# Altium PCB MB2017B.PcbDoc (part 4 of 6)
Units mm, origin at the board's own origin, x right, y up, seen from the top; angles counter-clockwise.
Board outline 148.19 x 169.19 mm, 4 copper layers (Top Layer, Mid Layer 1, Mid Layer 2, Bottom Layer), stack 1.498 mm thick; 458 components, 208 nets, 1223 pads, 6162 vias.
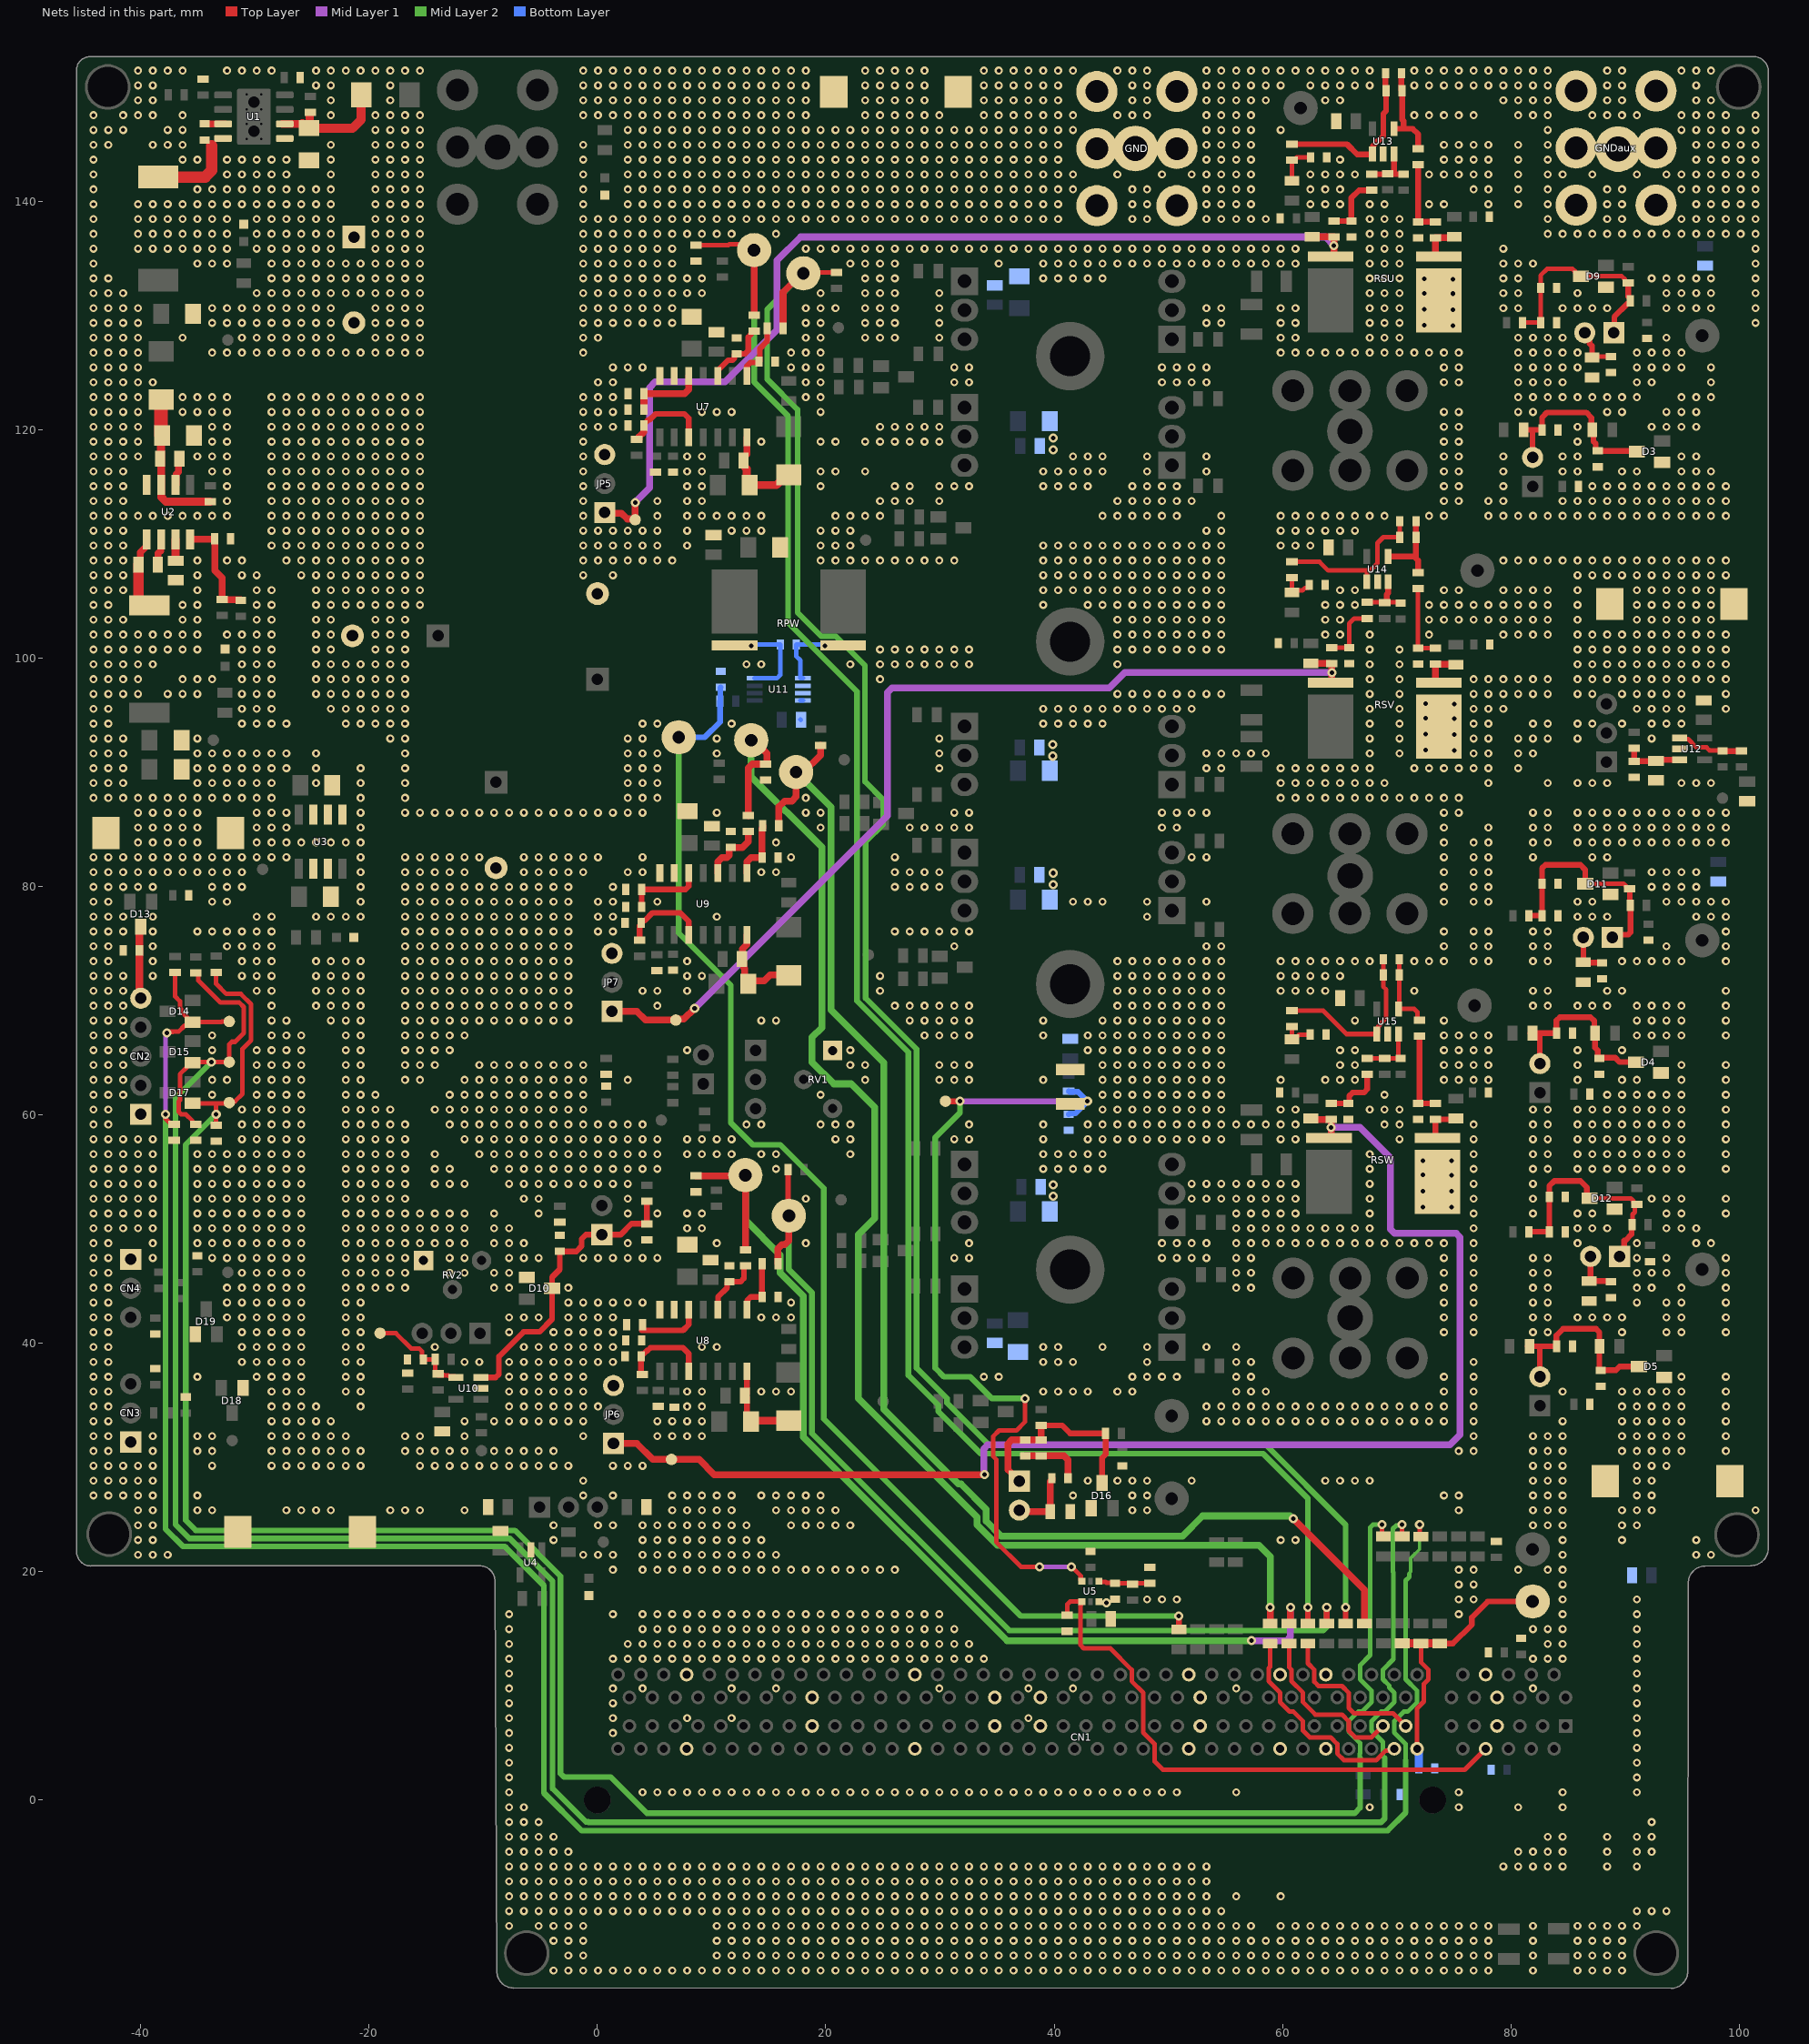
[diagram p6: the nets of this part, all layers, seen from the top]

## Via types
v1: diameter 0.7, hole 0.35, Top Layer to Bottom Layer, tented both sides, 5935 vias
v2: diameter 0.8, hole 0.4, Top Layer to Bottom Layer, tented both sides, 216 vias
v3: diameter 1, hole 0.5, Top Layer to Bottom Layer, tented both sides, 9 vias
v4: diameter 0.8, hole 0.4, Top Layer to Bottom Layer, 2 vias

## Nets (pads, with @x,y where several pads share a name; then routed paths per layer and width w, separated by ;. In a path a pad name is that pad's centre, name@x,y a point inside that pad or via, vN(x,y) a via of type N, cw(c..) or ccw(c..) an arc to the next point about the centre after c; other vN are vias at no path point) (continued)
GND: (continued)
  other v1: 48.147,112.484 49.447,112.484 50.747,112.484 54.647,112.484 59.847,112.484 61.147,112.484 62.447,112.484 63.747,112.484 65.047,112.484 66.347,112.484 67.647,112.484 68.947,112.484 72.847,112.484 74.147,112.484 78.047,112.484 79.347,112.484 80.647,112.484 81.947,112.484 83.247,112.484 84.547,112.484 85.847,112.484 87.147,112.484 88.447,112.484 89.747,112.484 91.047,112.484 92.347,112.484 93.647,112.484 94.947,112.484 96.247,112.484 97.547,112.484 98.847,112.484 -44.153,113.784 -42.853,113.784 -41.553,113.784 -32.453,113.784 -28.553,113.784 -27.253,113.784 -25.953,113.784 -24.653,113.784 -23.353,113.784 -22.053,113.784 -20.753,113.784 -19.453,113.784 -18.153,113.784 -16.853,113.784 -15.553,113.784 -1.253,113.784 5.247,113.784 7.847,113.784 9.147,113.784 24.747,113.784 26.047,113.784 27.347,113.784 29.947,113.784 45.547,113.784 46.847,113.784 48.147,113.784 49.447,113.784 50.747,113.784 52.047,113.784 74.147,113.784 75.447,113.784 78.047,113.784 79.347,113.784 84.547,113.784 85.847,113.784 87.147,113.784 88.447,113.784 89.747,113.784 91.047,113.784 92.347,113.784 93.647,113.784 94.947,113.784 96.247,113.784 97.547,113.784 98.847,113.784 -44.153,115.084 -42.853,115.084 -41.553,115.084 -32.453,115.084 -28.553,115.084 -27.253,115.084 -25.953,115.084 -24.653,115.084 -23.353,115.084 -22.053,115.084 -20.753,115.084 -19.453,115.084 -18.153,115.084 -16.853,115.084 -15.553,115.084 -1.253,115.084 7.847,115.084 9.147,115.084 19.547,115.084 26.047,115.084 27.347,115.084 29.947,115.084 31.247,115.084 32.547,115.084 39.047,115.084 40.347,115.084 41.647,115.084 42.947,115.084 46.847,115.084 48.147,115.084 49.447,115.084 50.747,115.084 74.147,115.084 75.447,115.084 79.347,115.084 87.147,115.084 88.447,115.084 89.747,115.084 91.047,115.084 92.347,115.084 93.647,115.084 94.947,115.084 96.247,115.084 97.547,115.084 98.847,115.084 -44.153,116.384 -42.853,116.384 -41.553,116.384 -33.753,116.384 -32.453,116.384 -28.553,116.384 -27.253,116.384 -25.953,116.384 -24.653,116.384 -23.353,116.384 -22.053,116.384 -20.753,116.384 -19.453,116.384 -18.153,116.384 -16.853,116.384 -15.553,116.384 -1.253,116.384 7.847,116.384 9.147,116.384 19.547,116.384 20.847,116.384 23.447,116.384 39.047,116.384 40.347,116.384 41.647,116.384 42.947,116.384 44.247,116.384 48.147,116.384 53.347,116.384 74.147,116.384 75.447,116.384 79.347,116.384 84.547,116.384 85.847,116.384 89.747,116.384 91.047,116.384 94.947,116.384 96.247,116.384 97.547,116.384 -44.153,117.684 -42.853,117.684 -41.553,117.684 -40.253,117.684 -35.053,117.684 -33.753,117.684 -32.453,117.684 -28.553,117.684 -27.253,117.684 -25.953,117.684 -24.653,117.684 -23.353,117.684 -22.053,117.684 -20.753,117.684 -19.453,117.684 -18.153,117.684 -16.853,117.684 -15.553,117.684 -1.253,117.684 7.847,117.684 9.147,117.684 41.647,117.684 42.947,117.684 44.247,117.684 48.147,117.684 53.347,117.684 74.147,117.684 75.447,117.684 79.347,117.684 84.547,117.684 85.847,117.684 94.947,117.684 96.247,117.684 -44.153,118.984 -42.853,118.984 -41.553,118.984 -40.253,118.984 -33.753,118.984 -32.453,118.984 -28.553,118.984 -27.253,118.984 -25.953,118.984 -24.653,118.984 -23.353,118.984 -22.053,118.984 -20.753,118.984 -19.453,118.984 -18.153,118.984 -16.853,118.984 -15.553,118.984 -1.253,118.984 14.347,118.984 19.547,118.984 20.847,118.984 23.447,118.984 24.747,118.984 26.047,118.984 27.347,118.984 28.647,118.984 29.947,118.984 74.147,118.984 75.447,118.984 85.847,118.984 -44.153,120.284 -42.853,120.284 -41.553,120.284 -40.253,120.284 -33.753,120.284 -32.453,120.284 -28.553,120.284 -27.253,120.284 -25.953,120.284 -24.653,120.284 -23.353,120.284 -22.053,120.284 -20.753,120.284 -19.453,120.284 -18.153,120.284 -16.853,120.284 -15.553,120.284 -1.253,120.284 0.047,120.284 1.347,120.284 24.747,120.284 26.047,120.284 27.347,120.284 28.647,120.284 29.947,120.284 74.147,120.284 75.447,120.284 85.847,120.284 92.347,120.284 93.647,120.284 94.947,120.284 96.247,120.284 -44.153,121.584 -42.853,121.584 -41.553,121.584 -40.253,121.584 -36.353,121.584 -35.053,121.584 -33.753,121.584 -32.453,121.584 -28.553,121.584 -27.253,121.584 -25.953,121.584 -24.653,121.584 -23.353,121.584 -22.053,121.584 -20.753,121.584 -19.453,121.584 -18.153,121.584 -16.853,121.584 -15.553,121.584 -1.253,121.584 0.047,121.584 1.347,121.584 9.147,121.584 10.447,121.584 11.747,121.584 19.547,121.584 74.147,121.584 75.447,121.584 80.647,121.584 81.947,121.584 88.447,121.584 89.747,121.584 93.647,121.584 94.947,121.584 96.247,121.584 -44.153,122.884 -42.853,122.884 -41.553,122.884 -40.253,122.884 -36.353,122.884 -35.053,122.884 -33.753,122.884 -32.453,122.884 -28.553,122.884 -27.253,122.884 -25.953,122.884 -24.653,122.884 -23.353,122.884 -22.053,122.884 -20.753,122.884 -19.453,122.884 -18.153,122.884 -16.853,122.884 -15.553,122.884 -1.253,122.884 0.047,122.884 1.347,122.884 18.247,122.884 19.547,122.884 80.647,122.884 81.947,122.884 83.247,122.884 84.547,122.884 85.847,122.884 87.147,122.884 88.447,122.884 89.747,122.884 91.047,122.884 94.947,122.884 96.247,122.884 97.547,122.884 -44.153,124.184 -42.853,124.184 -41.553,124.184 -40.253,124.184 -38.953,124.184 0.047,124.184 1.347,124.184 18.247,124.184 19.547,124.184 31.247,124.184 32.547,124.184 49.447,124.184 50.747,124.184 52.047,124.184 53.347,124.184 74.147,124.184 75.447,124.184 80.647,124.184 81.947,124.184 83.247,124.184 84.547,124.184 91.047,124.184 92.347,124.184 97.547,124.184 -44.153,125.484 -42.853,125.484 -41.553,125.484 -40.253,125.484 1.347,125.484 2.647,125.484 3.947,125.484 16.947,125.484 18.247,125.484 19.547,125.484 31.247,125.484 32.547,125.484 49.447,125.484 50.747,125.484 52.047,125.484 53.347,125.484 74.147,125.484 75.447,125.484 80.647,125.484 81.947,125.484 83.247,125.484 84.547,125.484 85.847,125.484 91.047,125.484 92.347,125.484 93.647,125.484 94.947,125.484 97.547,125.484 -44.153,126.784 -42.853,126.784 -41.553,126.784 -40.253,126.784 -33.753,126.784 -32.453,126.784 -31.153,126.784 -29.853,126.784 -28.553,126.784 -27.253,126.784 -25.953,126.784 -24.653,126.784 -23.353,126.784 -22.053,126.784 -20.753,126.784 -19.453,126.784 -18.153,126.784 -16.853,126.784 -15.553,126.784 -1.253,126.784 16.947,126.784 18.247,126.784 19.547,126.784 59.847,126.784 61.147,126.784 62.447,126.784 63.747,126.784 65.047,126.784 66.347,126.784 67.647,126.784 68.947,126.784 70.247,126.784 71.547,126.784 72.847,126.784 74.147,126.784 75.447,126.784 80.647,126.784 81.947,126.784 83.247,126.784 84.547,126.784 85.847,126.784 91.047,126.784 92.347,126.784 93.647,126.784 94.947,126.784 -44.153,128.084 -42.853,128.084 -41.553,128.084 -40.253,128.084 -36.353,128.084 -31.153,128.084 -29.853,128.084 -28.553,128.084 -27.253,128.084 -25.953,128.084 -24.653,128.084 -23.353,128.084 -19.453,128.084 -18.153,128.084 -16.853,128.084 -15.553,128.084 -1.253,128.084 0.047,128.084 18.247,128.084 19.547,128.084 23.447,128.084 24.747,128.084 26.047,128.084 29.947,128.084 59.847,128.084 61.147,128.084 67.647,128.084 68.947,128.084 70.247,128.084 80.647,128.084 81.947,128.084 83.247,128.084 84.547,128.084 93.647,128.084 -44.153,129.384 -42.853,129.384 -41.553,129.384 -40.253,129.384 -33.753,129.384 -32.453,129.384 -31.153,129.384 -29.853,129.384 -28.553,129.384 -27.253,129.384 -25.953,129.384 -24.653,129.384 -23.353,129.384 -19.453,129.384 -18.153,129.384 -16.853,129.384 -15.553,129.384 -1.253,129.384 0.047,129.384 1.347,129.384 2.647,129.384 3.947,129.384 5.247,129.384 6.547,129.384 18.247,129.384 19.547,129.384 23.447,129.384 24.747,129.384 26.047,129.384 29.947,129.384 53.347,129.384 54.647,129.384 59.847,129.384 61.147,129.384 67.647,129.384 68.947,129.384 70.247,129.384 101.447,129.384 -44.153,130.684 -42.853,130.684 -41.553,130.684 -40.253,130.684 -33.753,130.684 -32.453,130.684 -31.153,130.684 -29.853,130.684 -28.553,130.684 -27.253,130.684 -25.953,130.684 -24.653,130.684 -23.353,130.684 -19.453,130.684 -18.153,130.684 -16.853,130.684 -15.553,130.684 -1.253,130.684 0.047,130.684 1.347,130.684 2.647,130.684 3.947,130.684 5.247,130.684 6.547,130.684 18.247,130.684 19.547,130.684 20.847,130.684 23.447,130.684 24.747,130.684 26.047,130.684 29.947,130.684 53.347,130.684 54.647,130.684 59.847,130.684 61.147,130.684 67.647,130.684 68.947,130.684 70.247,130.684 79.347,130.684 80.647,130.684 84.547,130.684 85.847,130.684 87.147,130.684 88.447,130.684 93.647,130.684 94.947,130.684 96.247,130.684 97.547,130.684 101.447,130.684 -44.153,131.984 -42.853,131.984 -41.553,131.984 -29.853,131.984 -28.553,131.984 -27.253,131.984 -25.953,131.984 -24.653,131.984 -23.353,131.984 -22.053,131.984 -20.753,131.984 -19.453,131.984 -18.153,131.984 -16.853,131.984 -15.553,131.984 -1.253,131.984 0.047,131.984 1.347,131.984 2.647,131.984 3.947,131.984 5.247,131.984 6.547,131.984 7.847,131.984 9.147,131.984 19.547,131.984 23.447,131.984 24.747,131.984 26.047,131.984 29.947,131.984 67.647,131.984 68.947,131.984 70.247,131.984 79.347,131.984 80.647,131.984 85.847,131.984 93.647,131.984 94.947,131.984 96.247,131.984 97.547,131.984 101.447,131.984 -44.153,133.284 -42.853,133.284 -28.553,133.284 -27.253,133.284 -25.953,133.284 -24.653,133.284 -23.353,133.284 -22.053,133.284 -20.753,133.284 -19.453,133.284 -18.153,133.284 -16.853,133.284 -15.553,133.284 -1.253,133.284 0.047,133.284 1.347,133.284 2.647,133.284 3.947,133.284 5.247,133.284 6.547,133.284 7.847,133.284 9.147,133.284 23.447,133.284 24.747,133.284 26.047,133.284 39.047,133.284 40.347,133.284 41.647,133.284 42.947,133.284 44.247,133.284 67.647,133.284 68.947,133.284 70.247,133.284 79.347,133.284 80.647,133.284 92.347,133.284 93.647,133.284 94.947,133.284 96.247,133.284 97.547,133.284 101.447,133.284 -44.153,134.584 -35.053,134.584 -33.753,134.584 -32.453,134.584 -28.553,134.584 -27.253,134.584 -25.953,134.584 -24.653,134.584 -23.353,134.584 -22.053,134.584 -20.753,134.584 -19.453,134.584 -18.153,134.584 -16.853,134.584 -15.553,134.584 -1.253,134.584 0.047,134.584 1.347,134.584 2.647,134.584 3.947,134.584 5.247,134.584 6.547,134.584 22.147,134.584 23.447,134.584 24.747,134.584 26.047,134.584 35.147,134.584 39.047,134.584 40.347,134.584 41.647,134.584 42.947,134.584 44.247,134.584 45.547,134.584 46.847,134.584 48.147,134.584 49.447,134.584 50.747,134.584 52.047,134.584 53.347,134.584 54.647,134.584 55.947,134.584 57.247,134.584 58.547,134.584 59.847,134.584 61.147,134.584 67.647,134.584 68.947,134.584 70.247,134.584 79.347,134.584 80.647,134.584 81.947,134.584 101.447,134.584 -44.153,135.884 -40.253,135.884 -38.953,135.884 -37.653,135.884 -36.353,135.884 -35.053,135.884 -33.753,135.884 -32.453,135.884 -29.853,135.884 -28.553,135.884 -27.253,135.884 -25.953,135.884 -24.653,135.884 -23.353,135.884 -19.453,135.884 -18.153,135.884 -16.853,135.884 -15.553,135.884 -1.253,135.884 0.047,135.884 1.347,135.884 2.647,135.884 3.947,135.884 5.247,135.884 6.547,135.884 18.247,135.884 19.547,135.884 20.847,135.884 22.147,135.884 23.447,135.884 24.747,135.884 26.047,135.884 27.347,135.884 28.647,135.884 29.947,135.884 31.247,135.884 32.547,135.884 33.847,135.884 35.147,135.884 36.447,135.884 37.747,135.884 39.047,135.884 40.347,135.884 41.647,135.884 42.947,135.884 44.247,135.884 45.547,135.884 46.847,135.884 48.147,135.884 49.447,135.884 50.747,135.884 52.047,135.884 53.347,135.884 54.647,135.884 55.947,135.884 57.247,135.884 58.547,135.884 59.847,135.884 61.147,135.884 67.647,135.884 68.947,135.884 70.247,135.884 79.347,135.884 101.447,135.884 -44.153,137.184 -40.253,137.184 -38.953,137.184 -37.653,137.184 -36.353,137.184 -35.053,137.184 -33.753,137.184 -32.453,137.184 -29.853,137.184 -28.553,137.184 -27.253,137.184 -25.953,137.184 -24.653,137.184 -23.353,137.184 -19.453,137.184 -18.153,137.184 -16.853,137.184 -15.553,137.184 -1.253,137.184 0.047,137.184 1.347,137.184 2.647,137.184 3.947,137.184 5.247,137.184 6.547,137.184 7.847,137.184 9.147,137.184 10.447,137.184 11.747,137.184 15.647,137.184 67.647,137.184 68.947,137.184 70.247,137.184 83.247,137.184 84.547,137.184 85.847,137.184 87.147,137.184 88.447,137.184 89.747,137.184 91.047,137.184 92.347,137.184 93.647,137.184 94.947,137.184 96.247,137.184 97.547,137.184 98.847,137.184 100.147,137.184 101.447,137.184 -44.153,138.484 -40.253,138.484 -38.953,138.484 -37.653,138.484 -36.353,138.484 -35.053,138.484 -33.753,138.484 -32.453,138.484 -29.853,138.484 -28.553,138.484 -27.253,138.484 -25.953,138.484 -24.653,138.484 -23.353,138.484 -19.453,138.484 -18.153,138.484 -16.853,138.484 -15.553,138.484 -1.253,138.484 0.047,138.484 1.347,138.484 2.647,138.484 3.947,138.484 5.247,138.484 6.547,138.484 7.847,138.484 9.147,138.484 10.447,138.484 11.747,138.484 13.047,138.484 14.347,138.484 15.647,138.484 16.947,138.484 18.247,138.484 19.547,138.484 20.847,138.484 22.147,138.484 23.447,138.484 24.747,138.484 26.047,138.484 27.347,138.484 28.647,138.484 29.947,138.484 31.247,138.484 32.547,138.484 33.847,138.484 35.147,138.484 36.447,138.484 37.747,138.484 39.047,138.484 40.347,138.484 46.847,138.484 48.147,138.484 53.347,138.484 54.647,138.484 55.947,138.484 57.247,138.484 58.547,138.484 67.647,138.484 68.947,138.484 70.247,138.484 83.247,138.484 88.447,138.484 89.747,138.484 94.947,138.484 96.247,138.484 97.547,138.484 98.847,138.484 100.147,138.484 101.447,138.484 -44.153,139.784 -40.253,139.784 -38.953,139.784 -37.653,139.784 -36.353,139.784 -35.053,139.784 -33.753,139.784 -32.453,139.784 -31.153,139.784 -29.853,139.784 -28.553,139.784 -27.253,139.784 -25.953,139.784 -24.653,139.784 -23.353,139.784 -19.453,139.784 -18.153,139.784 -16.853,139.784 -15.553,139.784 -1.253,139.784 2.647,139.784 3.947,139.784 5.247,139.784 6.547,139.784 7.847,139.784 9.147,139.784 10.447,139.784 11.747,139.784 13.047,139.784 14.347,139.784 15.647,139.784 16.947,139.784 18.247,139.784 19.547,139.784 20.847,139.784 22.147,139.784 23.447,139.784 24.747,139.784 26.047,139.784 27.347,139.784 28.647,139.784 29.947,139.784 31.247,139.784 32.547,139.784 33.847,139.784 35.147,139.784 36.447,139.784 37.747,139.784 39.047,139.784 40.347,139.784 46.847,139.784 48.147,139.784 53.347,139.784 54.647,139.784 55.947,139.784 57.247,139.784 62.447,139.784 63.747,139.784 65.047,139.784 67.647,139.784 68.947,139.784 72.847,139.784 74.147,139.784 78.047,139.784 80.647,139.784 83.247,139.784 88.447,139.784 89.747,139.784 96.247,139.784 97.547,139.784 98.847,139.784 100.147,139.784 101.447,139.784 -44.153,141.084 -35.053,141.084 -33.753,141.084 -32.453,141.084 -31.153,141.084 -29.853,141.084 -28.553,141.084 -27.253,141.084 -25.953,141.084 -24.653,141.084 -23.353,141.084 -19.453,141.084 -18.153,141.084 -16.853,141.084 -15.553,141.084 -1.253,141.084 2.647,141.084 3.947,141.084 5.247,141.084 6.547,141.084 7.847,141.084 9.147,141.084 10.447,141.084 11.747,141.084 13.047,141.084 14.347,141.084 15.647,141.084 16.947,141.084 18.247,141.084 19.547,141.084 20.847,141.084 22.147,141.084 23.447,141.084 24.747,141.084 26.047,141.084 27.347,141.084 28.647,141.084 29.947,141.084 31.247,141.084 32.547,141.084 33.847,141.084 35.147,141.084 36.447,141.084 37.747,141.084 39.047,141.084 40.347,141.084 41.647,141.084 46.847,141.084 48.147,141.084 53.347,141.084 54.647,141.084 55.947,141.084 57.247,141.084 62.447,141.084 63.747,141.084 65.047,141.084 76.747,141.084 78.047,141.084 80.647,141.084 83.247,141.084 88.447,141.084 89.747,141.084 94.947,141.084 96.247,141.084 97.547,141.084 98.847,141.084 100.147,141.084 101.447,141.084 -44.153,142.384 -32.453,142.384 -31.153,142.384 -29.853,142.384 -28.553,142.384 -27.253,142.384 -23.353,142.384 -19.453,142.384 -18.153,142.384 -16.853,142.384 -15.553,142.384 -1.253,142.384 2.647,142.384 3.947,142.384 5.247,142.384 6.547,142.384 7.847,142.384 9.147,142.384 10.447,142.384 11.747,142.384 13.047,142.384 14.347,142.384 15.647,142.384 16.947,142.384 18.247,142.384 19.547,142.384 20.847,142.384 22.147,142.384 23.447,142.384 24.747,142.384 26.047,142.384 27.347,142.384 28.647,142.384 29.947,142.384 31.247,142.384 32.547,142.384 33.847,142.384 35.147,142.384 36.447,142.384 37.747,142.384 39.047,142.384 40.347,142.384 41.647,142.384 45.547,142.384 49.447,142.384 52.047,142.384 53.347,142.384 54.647,142.384 55.947,142.384 57.247,142.384 62.447,142.384 63.747,142.384 65.047,142.384 66.347,142.384 72.847,142.384 74.147,142.384 75.447,142.384 76.747,142.384 78.047,142.384 80.647,142.384 83.247,142.384 84.547,142.384 87.147,142.384 91.047,142.384 93.647,142.384 94.947,142.384 96.247,142.384 97.547,142.384 98.847,142.384 100.147,142.384 101.447,142.384 -44.153,143.684 -36.353,143.684 -35.053,143.684 -32.453,143.684 -31.153,143.684 -29.853,143.684 -28.553,143.684 -27.253,143.684 -23.353,143.684 -19.453,143.684 -18.153,143.684 -16.853,143.684 -15.553,143.684 -1.253,143.684 2.647,143.684 3.947,143.684 5.247,143.684 6.547,143.684 7.847,143.684 9.147,143.684 10.447,143.684 11.747,143.684 13.047,143.684 14.347,143.684 15.647,143.684 16.947,143.684 18.247,143.684 19.547,143.684 20.847,143.684 22.147,143.684 23.447,143.684 24.747,143.684 26.047,143.684 27.347,143.684 28.647,143.684 29.947,143.684 31.247,143.684 32.547,143.684 33.847,143.684 35.147,143.684 36.447,143.684 37.747,143.684 39.047,143.684 40.347,143.684 53.347,143.684 54.647,143.684 55.947,143.684 57.247,143.684 65.047,143.684 74.147,143.684 75.447,143.684 76.747,143.684 78.047,143.684 80.647,143.684 83.247,143.684 96.247,143.684 97.547,143.684 98.847,143.684 100.147,143.684 101.447,143.684 -44.153,144.984 -42.853,144.984 -38.953,144.984 -37.653,144.984 -36.353,144.984 -23.353,144.984 -19.453,144.984 -18.153,144.984 -16.853,144.984 -15.553,144.984 -1.253,144.984 2.647,144.984 3.947,144.984 5.247,144.984 6.547,144.984 7.847,144.984 9.147,144.984 10.447,144.984 11.747,144.984 13.047,144.984 14.347,144.984 15.647,144.984 16.947,144.984 18.247,144.984 19.547,144.984 20.847,144.984 22.147,144.984 23.447,144.984 24.747,144.984 26.047,144.984 27.347,144.984 28.647,144.984 29.947,144.984 31.247,144.984 32.547,144.984 33.847,144.984 35.147,144.984 36.447,144.984 37.747,144.984 39.047,144.984 40.347,144.984 53.347,144.984 54.647,144.984 55.947,144.984 57.247,144.984 74.147,144.984 75.447,144.984 76.747,144.984 78.047,144.984 80.647,144.984 83.247,144.984 96.247,144.984 97.547,144.984 98.847,144.984 100.147,144.984 101.447,144.984 -44.153,146.284 -42.853,146.284 -41.553,146.284 -37.653,146.284 -36.353,146.284 -19.453,146.284 -18.153,146.284 -16.853,146.284 -15.553,146.284 2.647,146.284 3.947,146.284 5.247,146.284 6.547,146.284 7.847,146.284 9.147,146.284 10.447,146.284 11.747,146.284 13.047,146.284 14.347,146.284 15.647,146.284 16.947,146.284 18.247,146.284 19.547,146.284 20.847,146.284 22.147,146.284 23.447,146.284 24.747,146.284 26.047,146.284 27.347,146.284 28.647,146.284 29.947,146.284 31.247,146.284 32.547,146.284 33.847,146.284 35.147,146.284 36.447,146.284 37.747,146.284 39.047,146.284 40.347,146.284 41.647,146.284 53.347,146.284 54.647,146.284 55.947,146.284 57.247,146.284 59.847,146.284 83.247,146.284 94.947,146.284 96.247,146.284 97.547,146.284 98.847,146.284 100.147,146.284 101.447,146.284 -44.153,147.584 -41.553,147.584 -40.253,147.584 -38.953,147.584 -36.353,147.584 -23.353,147.584 -19.453,147.584 -18.153,147.584 -16.853,147.584 -15.553,147.584 -1.253,147.584 0.047,147.584 1.347,147.584 2.647,147.584 3.947,147.584 5.247,147.584 6.547,147.584 7.847,147.584 9.147,147.584 10.447,147.584 11.747,147.584 13.047,147.584 14.347,147.584 15.647,147.584 16.947,147.584 18.247,147.584 23.447,147.584 24.747,147.584 26.047,147.584 27.347,147.584 28.647,147.584 29.947,147.584 33.847,147.584 35.147,147.584 36.447,147.584 37.747,147.584 39.047,147.584 40.347,147.584 41.647,147.584 45.547,147.584 46.847,147.584 48.147,147.584 53.347,147.584 54.647,147.584 55.947,147.584 57.247,147.584 71.547,147.584 72.847,147.584 74.147,147.584 75.447,147.584 76.747,147.584 80.647,147.584 81.947,147.584 83.247,147.584 87.147,147.584 88.447,147.584 89.747,147.584 91.047,147.584 94.947,147.584 96.247,147.584 97.547,147.584 98.847,147.584 101.447,147.584 -40.253,148.884 -38.953,148.884 -23.353,148.884 -18.153,148.884 -1.253,148.884 0.047,148.884 1.347,148.884 2.647,148.884 3.947,148.884 5.247,148.884 6.547,148.884 7.847,148.884 9.147,148.884 10.447,148.884 11.747,148.884 13.047,148.884 14.347,148.884 15.647,148.884 16.947,148.884 18.247,148.884 23.447,148.884 24.747,148.884 26.047,148.884 27.347,148.884 28.647,148.884 33.847,148.884 35.147,148.884 36.447,148.884 37.747,148.884 39.047,148.884 40.347,148.884 46.847,148.884 48.147,148.884 53.347,148.884 54.647,148.884 55.947,148.884 57.247,148.884 58.547,148.884 63.747,148.884 65.047,148.884 79.347,148.884 80.647,148.884 81.947,148.884 83.247,148.884 88.447,148.884 89.747,148.884 96.247,148.884 97.547,148.884 -40.253,150.184 -38.953,150.184 -24.653,150.184 -23.353,150.184 -18.153,150.184 -1.253,150.184 0.047,150.184 1.347,150.184 2.647,150.184 3.947,150.184 5.247,150.184 6.547,150.184 7.847,150.184 9.147,150.184 10.447,150.184 11.747,150.184 13.047,150.184 14.347,150.184 15.647,150.184 16.947,150.184 18.247,150.184 23.447,150.184 24.747,150.184 26.047,150.184 27.347,150.184 28.647,150.184 33.847,150.184 35.147,150.184 36.447,150.184 37.747,150.184 39.047,150.184 40.347,150.184 46.847,150.184 48.147,150.184 53.347,150.184 54.647,150.184 55.947,150.184 57.247,150.184 58.547,150.184 59.847,150.184 62.447,150.184 63.747,150.184 65.047,150.184 66.347,150.184 67.647,150.184 71.547,150.184 72.847,150.184 74.147,150.184 75.447,150.184 76.747,150.184 78.047,150.184 79.347,150.184 80.647,150.184 81.947,150.184 83.247,150.184 88.447,150.184 89.747,150.184 96.247,150.184 -40.253,151.484 -38.953,151.484 -37.653,151.484 -36.353,151.484 -32.453,151.484 -31.153,151.484 -29.853,151.484 -28.553,151.484 -24.653,151.484 -23.353,151.484 -22.053,151.484 -20.753,151.484 -19.453,151.484 -18.153,151.484 -16.853,151.484 -15.553,151.484 -1.253,151.484 0.047,151.484 1.347,151.484 2.647,151.484 3.947,151.484 5.247,151.484 6.547,151.484 7.847,151.484 9.147,151.484 10.447,151.484 11.747,151.484 13.047,151.484 14.347,151.484 15.647,151.484 16.947,151.484 18.247,151.484 23.447,151.484 24.747,151.484 26.047,151.484 27.347,151.484 28.647,151.484 33.847,151.484 35.147,151.484 36.447,151.484 37.747,151.484 39.047,151.484 40.347,151.484 41.647,151.484 45.547,151.484 46.847,151.484 48.147,151.484 53.347,151.484 54.647,151.484 55.947,151.484 57.247,151.484 58.547,151.484 59.847,151.484 61.147,151.484 62.447,151.484 63.747,151.484 65.047,151.484 66.347,151.484 67.647,151.484 71.547,151.484 72.847,151.484 74.147,151.484 75.447,151.484 76.747,151.484 78.047,151.484 79.347,151.484 80.647,151.484 81.947,151.484 83.247,151.484 88.447,151.484 89.747,151.484 94.947,151.484 96.247,151.484 97.547,151.484
  other v2: 74.803,51.943 72.308,51.957 39.921,52.88 74.803,53.34 72.308,53.354 39.921,53.896 74.803,54.737 72.308,54.751 74.803,56.007 72.308,56.021 39.921,80.185 39.921,81.201 39.878,91.44 75.057,91.948 72.562,91.962 39.878,92.456 75.057,93.345 72.562,93.359 75.057,94.742 72.562,94.756 75.057,96.012 72.562,96.026 39.921,118.285 39.921,119.301 74.93,129.159 72.435,129.173 74.93,130.556 72.435,130.57 74.93,131.953 72.435,131.967 74.93,133.223 72.435,133.237
"Hall H1": D14.1 H1.1 R43.2 R140.1 R147.2 | length 215.4
  Top Layer w0.4: v2(-37.846,60.071) -37.846,59.69 -37.461,59.305 -37.204,59.305 R147.2@-37.084,59.185 ; v2(-37.719,67.183) -37.604,67.298 -37.197,67.298 -37.185,67.31 -36.703,67.31 -36.175,67.838 -35.776,67.838 D14.1@-35.476,68.138 ; R140.1@-37.005,72.499 -37.005,70.406 -36.576,69.977 -36.576,69.372 -36.449,69.245 -36.449,69.068 -36.215,68.834 -36.21,68.834 -35.976,68.6 -35.976,68.438 -35.676,68.138 D14.1@-35.476,68.138 ; H1.1@-32.258,68.199 -32.893,68.199 -32.954,68.138 D14.1@-35.476,68.138 ; v2(72.009,24.13) 72.009,23.213 R43.2@72.136,23.086
  Mid Layer 1 w0.4: v2(-37.846,60.071) -37.846,67.056 v2(-37.719,67.183)
  Mid Layer 2 w0.3: 71.12,19.812 71.12,19.894 71.235,20.009 71.235,21.197 72.009,21.971 v2(72.009,24.13)
  Mid Layer 2 w0.4: 70.8,3.49 70.8,4.914 69.8,5.914 69.8,6.914 70.636,7.75 70.964,7.75 71.8,8.586 71.8,9.586 70.8,10.586 70.8,19.238 71.12,19.558 71.12,19.812
  Mid Layer 2 w0.5: v2(-37.846,60.071) -37.846,23.749 -36.322,22.225 -8.128,22.225 -4.699,18.796 -4.699,0.635 -1.397,-2.667 69.215,-2.667 70.8,-1.082 70.8,3.49
"Hall H2": D15.1 H2.1 R45.2 R141.1 R148.2 | length 220.5
  Top Layer w0.4: R148.2@-35.179,59.185 -35.359,59.185 -35.479,59.305 -35.479,59.485 -36.065,60.071 -36.469,60.071 -36.703,60.305 -36.703,61.183 -36.576,61.31 -36.576,63.592 -35.976,64.192 -35.976,64.282 -35.676,64.582 D15.1@-35.476,64.582 -35.415,64.643 v2(-33.836,64.643) H2.1@-32.258,64.643 -32.258,66.187 -32.024,66.421 -31.75,66.421 -30.988,67.183 -30.988,69.469 -31.369,69.85 -33.02,69.85 -34.966,71.796 -34.966,72.332 -35.086,72.452 R141.1@-35.179,72.452 ; R45.2@70.485,23.1 v2(70.485,24.13)
  Mid Layer 2 w0.4: 68.961,3.683 68.8,3.844 68.8,5.086 67.8,6.086 67.8,6.914 68.636,7.75 68.964,7.75 69.8,8.586 69.8,9.414 69.342,9.872 69.342,10.044 68.8,10.586 68.8,11.414 69.723,12.337 69.723,19.951 69.685,19.989 69.685,23.771 69.967,24.053 70.408,24.053 v2(70.485,24.13)
  Mid Layer 2 w0.5: v2(-33.836,64.643) -36.957,61.522 -36.957,24.13 -35.752,22.925 -7.685,22.925 -3.937,19.177 -3.937,1.016 -1.016,-1.905 -0.824,-1.905 -0.801,-1.928 68.645,-1.928 68.961,-1.612 68.961,3.683
"Hall H3": D17.1 H3.1 R46.1 R142.1 R149.2 | length 209.1
  Top Layer w0.4: D17.1@-35.476,61.026 -33.401,61.026 ; R149.2@-33.401,59.12 v2(-33.401,60.073) -33.401,61.026 ; R142.1@-33.401,72.514 -33.401,71.501 -32.512,70.612 -31.242,70.612 -30.353,69.723 -30.353,66.548 -31.115,65.786 -31.115,61.849 -31.762,61.202 -32.143,61.202 H3.1@-32.258,61.087 -32.319,61.026 -33.401,61.026 ; v2(68.707,24.13) 68.707,23.227 R46.1@68.834,23.1
  Mid Layer 2 w0.4: 66.802,3.683 66.765,3.72 66.765,4.051 66.8,4.086 66.8,4.914 66.8,5 65.8,6 65.8,6.914 66.636,7.75 66.964,7.75 67.8,8.586 67.8,9.586 66.8,10.586 66.8,11.414 66.802,11.416 66.802,11.811 67.691,12.7 67.691,23.876 67.945,24.13 v2(68.707,24.13)
  Mid Layer 2 w0.5: v2(-33.401,60.073) -36.068,57.406 -36.068,24.511 -35.182,23.625 -7.395,23.625 -7.392,23.622 -7.239,23.622 -3.237,19.62 -3.237,2.325 -2.944,2.032 1.143,2.032 4.318,-1.143 66.335,-1.143 66.802,-0.676 66.802,3.683
HinU: HinU.1 R34.2 R53.1 R68.2 | length 165.9
  Top Layer w0.4: R53.1@8.636,136.209 11.495,136.209 11.557,136.271 12.182,136.271 12.192,136.26 13.219,136.26 HinU.1@13.716,135.763
  Top Layer w0.5: R34.2@62.23,15.48 v2(62.23,16.891)
  Top Layer w0.6: R68.2@13.716,130.051 HinU.1@13.716,135.763
  Mid Layer 2 w0.5: HinU.1@13.716,135.763 13.716,124.206 16.702,121.22 16.702,103.124 22.733,97.093 22.733,70.003 27.24,65.496 27.24,37.208 29.858,34.59 29.858,34.049 33.554,30.353 58.319,30.353 62.23,26.442 v2(62.23,16.891)
HinV: HinV.1 R37.2 R58.2 R95.2 | length 121.1
  Top Layer w0.6: R95.2@13.208,86.236 13.208,90.392 13.559,90.743 R58.2@14.732,90.743 14.839,90.743 14.859,90.763 14.859,91.694 13.716,92.837 HinV.1@13.462,92.837 ; R37.2@58.928,15.48 v2(58.928,16.891)
  Mid Layer 2 w0.6: HinV.1@13.462,92.837 13.462,89.662 19.647,83.477 19.647,67.653 18.796,66.802 18.796,64.643 20.701,62.738 22.225,62.738 24.29,60.673 24.29,50.96 22.86,49.53 22.86,35.179 33.248,24.791 33.248,24.123 35.045,22.326 57.938,22.326 58.928,21.336 v2(58.928,16.891)
HinW: HinW.1 R40.2 R56.2 R104.2 | length 90
  Top Layer w0.6: R56.2@8.636,54.675 12.892,54.675 HinW.1@12.954,54.737 R104.2@12.954,48.198 ; R40.2@60.579,15.48 60.581,15.48 60.706,15.605 v2(60.706,16.891)
  Mid Layer 1 w0.6: v2@57.331,13.97 60.355,13.97 60.706,14.321 v2(60.706,16.891)
  Mid Layer 2 w0.6: HinW.1@12.954,54.737 12.954,50.8 16.014,47.74 16.014,46.171 18.046,44.139 18.046,31.82 35.896,13.97 v2@57.223,13.97
  other v2: 57.277,13.97
Icc_Current: C85.2 Icc_Current.1 R52.2 R128.2 | length 113
  Top Layer w0.5: R52.2@50.927,14.958 v2(50.927,16.129)
  Mid Layer 2 w0.5: Icc_Current.1@7.112,93.091 7.112,75.946 11.684,71.374 11.684,59.309 13.589,57.404 16.002,57.404 19.812,53.594 19.812,33.401 37.084,16.129 v2(50.927,16.129)
  Bottom Layer w0.5: Icc_Current.1@7.112,93.091 9.398,93.091 10.73,94.423 R128.2@10.73,96.266 10.763,96.299 10.763,97.438 C85.2@10.795,97.471
Icc_Power+: C82.2 RPW.S1 U11.8 | length 7.6
  Bottom Layer w0.4: v4(13.462,101.092) 13.589,101.219 C82.2@15.999,101.219 15.999,98.549 15.707,98.257 U11.8@13.75,98.257
Icc_Power-: C82.1 RPW.S2 U11.1 | length 5.9
  Bottom Layer w0.4: U11.1@18,98.257 17.78,98.257 17.78,99.822 17.399,100.203 C82.1@17.399,101.219 19.704,101.219 19.831,101.092 v4(19.939,101.092)
ID: CN1.A08 R17.2 U5.1 | length 50.5
  Top Layer w0.4: R17.2@41.148,16.194 41.148,17.145 41.391,17.388 U5.1@42.43,17.388 42.33,17.288 42.33,17.093 42.291,17.054 42.291,13.589 42.584,13.296 44.919,13.296 46.8,11.414 46.8,10.414 47.8,9.414 47.8,8.586 47.8,6.086 47.8,5.914 48.8,4.914 48.8,3.397 49.53,2.667 75.967,2.667 CN1.A08@77.8,4.5
IoutU+: IoutU+.1 JP5.1 R145.1 R152.1 RSU.S2 | length 87.9
  Top Layer w0.6: JP5.1@0.635,112.776 0.712,112.699 2.109,112.699 2.595,112.213 3.23,112.213 3.302,112.286 v2(3.302,113.665) ; R145.1@62.611,136.92 64.499,136.92 R152.1@64.516,136.903 v2(64.516,136.147) 64.516,135.391 64.366,135.241 RSU.S2@64.262,135.241
  Mid Layer 1 w0.6: v2(3.302,113.665) 4.561,114.924 4.561,123.717 5.05,124.206 11.173,124.206 15.716,128.749 15.716,134.842 17.785,136.911 63.752,136.911 v2(64.516,136.147)
IoutU-: R156.1 R159.2 RSU.S1 | length 3.6
  Top Layer w0.6: RSU.S1@73.762,135.241 73.556,135.241 73.406,135.391 R156.1@73.406,136.841 74.964,136.841 R159.2@75.057,136.934
IoutV+: IoutV+.1 JP7.1 R161.1 R165.1 RSV.S2 | length 85.8
  Top Layer w0.6: JP7.1@1.27,69.088 3.429,69.088 4.191,68.326 IoutV+.1@6.858,68.326 6.93,68.398 7.565,68.398 v2(8.509,69.342) ; R161.1@62.484,99.568 64.12,99.568 64.155,99.533 R165.1@64.335,99.533 v2(64.335,98.755) 64.335,97.976 RSV.S2@64.262,97.903
  Mid Layer 1 w0.6: v2(8.509,69.342) 25.4,86.233 25.4,97.028 25.781,97.409 44.831,97.409 46.177,98.755 v2(64.335,98.755)
IoutV-: R174.1 R181.2 RSV.S1 | length 3.7
  Top Layer w0.4: R181.2@75.136,99.503 R181.2@75.184,99.455
  Top Layer w0.6: RSV.S1@73.762,97.903 73.556,97.903 73.406,98.053 R174.1@73.406,99.503 R181.2@75.136,99.503
IoutW+: IoutW+.1 JP6.1 R163.1 R166.1 RSW.S2 | length 118
  Top Layer w0.6: JP6.1@1.397,31.242 3.429,31.242 4.826,29.845 IoutW+.1@6.477,29.845 8.89,29.845 10.221,28.514 v2(33.909,28.514) ; R163.1@62.484,59.704 62.563,59.625 R166.1@64.155,59.625 ; RSW.S2@64.135,58.039 64.262,58.166 v2(64.262,58.928) 64.262,59.605 64.242,59.625 R166.1@64.155,59.625 ; R166.1@64.262,59.625 R166.1@64.155,59.625
  Mid Layer 1 w0.6: v2(33.909,28.514) 33.832,28.591 33.832,30.764 34.184,31.115 74.676,31.115 75.565,32.004 75.565,49.306 75.214,49.657 69.82,49.657 69.469,50.008 69.469,56.261 66.802,58.928 v2(64.262,58.928)
IoutW-: R176.1 R182.2 RSW.S1 | length 3.5
  Top Layer w0.5: RSW.S1@73.635,58.039 73.606,58.039 73.406,58.239 R176.1@73.406,59.625 75.105,59.625 R182.2@75.184,59.704
LinU: LinU.1 R35.1 R55.1 R72.2 | length 165.4
  Top Layer w0.4: LinU.1@17.907,133.731 LinU.1@18.034,133.731 18.099,133.796 R55.1@20.955,133.796
  Top Layer w0.5: R35.1@65.532,15.48 v2(65.532,16.891)
  Top Layer w0.6: R72.2@16.256,128.905 16.256,132.08 LinU.1@17.907,133.731
  Mid Layer 2 w0.5: LinU.1@18.034,133.731 14.859,130.556 14.859,124.46 17.526,121.793 17.526,104.013 19.597,101.942 20.867,101.942 23.433,99.376 23.433,89.216 25.019,87.63 25.019,85.471 23.495,83.947 23.495,70.231 27.94,65.786 27.94,37.846 30.607,35.179 30.607,34.798 34.29,31.115 58.547,31.115 65.532,24.13 v2(65.532,16.891)
LinV: LinV.1 R38.1 R54.1 R99.2 | length 122
  Top Layer w0.6: R99.2@15.878,85.344 15.878,86.998 16.383,87.503 17.018,87.503 17.399,87.884 LinV.1@17.399,90.043 18.048,90.043 19.531,91.525 19.531,92.371 19.551,92.391 R54.1@19.558,92.391 ; v2(60.96,24.638) 67.183,18.415 R38.1@67.183,15.48
  Mid Layer 2 w0.6: LinV.1@17.399,90.043 20.447,86.995 20.447,69.215 25.09,64.572 25.09,34.219 31.623,27.686 31.832,27.686 34.048,25.47 34.048,24.454 35.376,23.126 51.238,23.126 53.004,24.892 60.652,24.892 60.906,24.638 v2(60.96,24.638)
LinW: LinW.1 R41.1 R57.2 R105.2 | length 84.2
  Top Layer w0.5: R57.2@16.699,55.245 16.699,51.246 LinW.1@16.764,51.181 ; R41.1@63.881,15.48 v2(63.881,16.891)
  Top Layer w0.6: R105.2@15.813,46.99 15.813,48.29 16.164,48.641 16.413,48.641 16.764,48.992 LinW.1@16.764,51.181
  Mid Layer 2 w0.5: LinW.1@16.764,51.181 16.764,46.482 18.796,44.45 18.796,32.131 36.068,14.859 63.588,14.859 63.881,15.152 v2(63.881,16.891)
NetC1_1: C1.1 L1.1 U1.8 | length 7.1
  Top Layer w1: L1.1@-38.481,142.168 -34.368,142.168 -33.782,142.754 -33.782,144.907
NetC1_2: C1.2 U1.7 | length 1.8
  Top Layer w0.6: C1.2@-34.417,146.815 -32.602,146.815 U1.7@-32.599,146.812
NetC2_1: C2.1 C3.2 D1.1 R1.1 U1.2 | length 10.9
  Top Layer w0.7: U1.2@-27.599,146.812 C3.2@-25.838,146.812 ; C3.2@-25.209,146.5 R1.1@-25.209,147.764
  Top Layer w0.8: C3.2@-25.838,146.812 -25.463,146.437 C3.2@-25.273,146.437 ; C3.2@-25.209,146.5 C3.2@-25.273,146.437 ; D1.1@-20.701,149.352 -20.701,147.193 -21.457,146.437 C3.2@-25.273,146.437
NetC5_2: C5.2 C6.2 D2.1 R7.1 U2.7 | length 13.1
  Top Layer w0.7: C6.2@-38.227,119.581 -38.236,119.572 -38.236,117.554 C5.2@-38.315,117.475 -38.227,117.387 U2.7@-38.227,115.189 -38.227,114.137 -37.817,113.727 R7.1@-33.909,113.727
  Top Layer w1.2: C6.2@-38.227,119.581 D2.1@-38.227,122.682
NetC7_1: C7.1 L2.1 U2.1 | length 6.8
  Top Layer w0.6: C7.1@-40.22,108.204 -40.07,108.354 -40.07,109.273 -39.869,109.474 -39.848,109.474 -39.497,109.825 U2.1@-39.497,110.439
  Top Layer w0.9: C7.1@-40.22,108.204 -40.22,105.089 -39.78,104.649 L2.1@-39.243,104.649
NetC7_2: C7.2 U2.2 | length 2.4
  Top Layer w0.6: C7.2@-38.52,108.204 -38.481,108.243 -38.481,109.22 -38.277,109.424 -38.277,110.389 U2.2@-38.227,110.439
NetC10_2: C10.2 U2.3 | length 1.9
  Top Layer w0.7: C10.2@-36.957,108.546 U2.3@-36.957,110.439
NetC11_1: C11.1 R8.1 R10.2 U2.4 | length 9.4
  Top Layer w0.6: U2.4@-35.687,110.439 -33.551,110.439 R10.2@-33.531,110.459 ; R10.2@-33.531,110.49 R10.2@-33.531,110.459 ; C11.1@-31.242,105.159 R8.1@-32.893,105.159 -32.893,107.061 -33.531,107.699 R10.2@-33.531,110.459
NetC19_2: C19.2 NTC1.2 R15.2 Temp.1 U5.6 | length 75.3
  Top Layer w0.4: v2(37.465,35.179) 37.465,33.147 36.703,32.385 35.179,32.385 34.671,31.877 34.671,30.099 34.925,29.845 34.925,22.606 37.084,20.447 v2(38.735,20.447) ; v2(41.529,20.447) 42.33,19.646 42.33,19.288 U5.6@42.43,19.188
  Top Layer w0.5: Temp.1@30.48,61.214 v2(31.75,61.214) ; NTC1.2@41.402,60.984 41.575,61.157 42.869,61.157 v2(42.926,61.214)
  Mid Layer 1 w0.4: v2(38.735,20.447) v2(41.529,20.447)
  Mid Layer 1 w0.5: v2(31.75,61.214) v2(42.926,61.214)
  Mid Layer 2 w0.5: v2(31.75,61.214) 31.75,60.198 29.591,58.039 29.591,37.846 30.353,37.084 32.639,37.084 34.544,35.179 v2(37.465,35.179)
  Bottom Layer w0.5: C19.2@41.275,60.071 41.345,60.141 41.853,60.141 v2(42.926,61.214) 42.098,62.042 41.333,62.042 R15.2@41.275,62.1
NetC21_2: C21.2 R14.1 R16.2 U5.4 | length 4.6
  Top Layer w0.4: U5.4@43.93,19.188 44,19.118 44.509,19.118 44.577,19.05 45.277,19.05 C21.2@45.339,18.988 46.798,18.988 R14.1@46.863,18.923 46.925,18.985 R16.2@48.387,18.985
NetC22_2: C22.2 D3.3 JP2.2 R18.1 R21.2 R25.2 | length 16.7
  Top Layer w0.5: R18.1@80.964,120.015 81.852,120.015 ; JP2.2@81.915,117.602 81.915,119.951 81.852,120.015 ; D3.3@91.059,118.11 90.994,118.175 C22.2@87.63,118.175 87.509,118.175 87.439,118.245 87.439,118.809 87.249,118.999 87.249,119.902 R21.2@87.136,120.015 87.069,120.082 87.069,121.084 86.614,121.539 83.185,121.539 82.739,121.093 R25.2@82.739,120.015 81.852,120.015
NetC23_2: C23.2 D4.3 JP3.2 R19.1 R22.2 R27.2 | length 16.5
  Top Layer w0.5: R19.1@81.726,67.183 82.55,67.183 ; JP3.2@82.55,64.516 82.55,67.183 ; D4.3@90.975,64.643 89.535,64.643 89.154,65.024 87.819,65.024 C23.2@87.757,64.962 87.699,64.962 87.629,65.032 87.629,65.66 87.39,65.899 R22.2@87.39,67.183 87.323,67.25 87.323,68.252 86.995,68.58 84.302,68.58 84.009,68.287 R27.2@84.009,67.183 82.55,67.183
NetC24_2: C24.2 D5.3 JP4.2 R20.1 R23.2 R29.2 | length 17.1
  Top Layer w0.5: R20.1@81.472,39.751 82.55,39.751 ; JP4.2@82.55,37.084 82.55,39.751 ; D5.3@91.229,37.973 89.535,37.973 89.219,37.657 C24.2@87.884,37.657 87.841,37.657 87.771,37.727 R23.2@87.771,39.751 87.771,40.982 87.478,41.275 84.582,41.275 84.009,40.702 R29.2@84.009,39.751 82.55,39.751
NetC28_1: C28.1 CN1.A12 Overcurrent.1 R30.1 R31.1 R32.1 | length 25
  Top Layer w0.4: CN1.A12@71.8,4.5 71.8,8.046 72.39,8.636 72.39,10.176 72.8,10.586 72.8,11.414 72.136,12.078 R31.1@72.136,13.716
  Top Layer w0.5: R30.1@73.787,13.716 74.93,13.716 76.581,15.367 76.581,16.002 77.978,17.399 Overcurrent.1@81.915,17.399
  Top Layer w0.7: R32.1@70.485,13.744 73.759,13.744 R30.1@73.787,13.716
  Bottom Layer w0.7: CN1.A12@71.8,4.5 71.8,4.365 71.944,4.221 C28.1@71.944,2.794
NetC39_2: C39.2 C40.2 D6.1 U7.14 | length 8.3
  Top Layer w0.6: C39.2@12.788,117.348 12.788,117.598 13.081,117.891 U7.14@13.081,119.347
  Top Layer w0.7: C39.2@12.788,117.348 12.888,117.248 12.888,116.779 13.081,116.586 13.081,115.446 C40.2@13.338,115.189 15.675,115.189 16.564,116.078 D6.1@16.764,116.078
NetC41_2: C41.2 R68.1 U7.3 | length 6
  Top Layer w0.5: U7.3@10.541,124.747 10.541,125.222 11.292,125.973 11.3,125.973 11.438,126.111 11.811,126.111 11.997,126.297 11.997,126.611 12.067,126.681 C41.2@12.192,126.681 12.915,126.682 13.208,126.975 13.208,128.143 13.466,128.401 13.466,128.581 13.536,128.651 R68.1@13.716,128.651
NetC42_1: C42.1 R77.2 U7.10 | length 7.8
  Top Layer w0.5: C42.1@4.064,120.396 4.064,120.521 4.134,120.591 4.152,120.591 4.459,120.898 4.57,120.898 5.084,121.412 7.62,121.412 8.001,121.031 U7.10@8.001,119.347
  Top Layer w0.6: R77.2@3.429,119.191 3.609,119.191 3.629,119.211 3.629,119.391 4.044,119.806 4.044,120.376 C42.1@4.064,120.396
NetC43_2: C43.2 R72.1 U7.1 | length 5.4
  Top Layer w0.4: U7.1@13.081,124.747 U7.1@13.181,124.847
  Top Layer w0.5: U7.1@13.081,124.747 13.081,125.603 13.398,125.92 14.095,125.92 14.224,126.049 14.224,127.127 14.856,127.759 R72.1@14.856,128.905
NetC44_2: C44.2 R74.2 U7.5 | length 6.7
  Top Layer w0.6: C44.2@4.064,121.793 4.067,121.796 R74.2@4.067,123.19 7.65,123.19 8.001,123.541 U7.5@8.001,124.747
NetC46_2: C46.2 C48.2 D7.1 U8.14 | length 8
  Top Layer w0.5: U8.14@13.081,37.559 13.081,35.599 C48.2@12.915,35.433 13.081,35.267 13.081,33.531 C46.2@13.465,33.147
  Top Layer w0.7: C46.2@13.465,33.147 13.563,33.245 D7.1@16.764,33.245
NetC47_1: C47.1 R79.2 U8.10 | length 8
  Top Layer w0.5: R79.2@3.937,37.276 3.88,37.276 3.81,37.346 3.81,38.859 C47.1@3.813,38.862 3.813,38.987 3.883,39.057 4.008,39.057 4.315,39.364 4.381,39.364 4.641,39.624 7.493,39.624 8.001,39.116 U8.10@8.001,37.559
NetC61_2: C61.2 C62.2 D8.1 U9.14 | length 8.4
  Top Layer w0.6: U9.14@13.081,75.786 13.081,74.93 12.7,74.549 12.7,73.699 C61.2@12.661,73.66 12.811,73.51 12.811,72.925 12.888,72.848 12.888,71.827 12.96,71.755 14.605,71.755 15.111,72.261 16.737,72.261 D8.1@16.764,72.234
NetC63_2: C63.2 R95.1 U9.3 | length 5.7
  Top Layer w0.6: U9.3@10.541,81.186 10.541,82.199 10.892,82.55 11.333,82.55 11.539,82.756 11.539,83.416 11.559,83.436 C63.2@11.684,83.436 12.697,83.436 13.208,83.947 R95.1@13.208,84.836
NetC64_2: C64.2 R96.1 U8.5 | length 5.6
  Top Layer w0.5: 3.875,41.148 7.493,41.148 8.001,41.656 U8.5@8.001,42.959
NetC66_1: C66.1 R102.2 U9.10 | length 7.7
  Top Layer w0.5: R102.2@3.683,75.311 3.683,76.58 3.813,76.71 C66.1@3.813,76.835 3.813,76.96 3.883,77.03 4.132,77.03 4.826,77.724 7.239,77.724 8.001,76.962 U9.10@8.001,75.786
NetC67_2: C67.2 R99.1 U9.1 | length 5.3
  Top Layer w0.6: U9.1@13.081,81.186 13.081,82.199 13.432,82.55 C67.2@14.413,82.55 14.413,85.099 14.478,85.164 R99.1@14.478,85.344
NetC68_2: C68.2 R101.2 U9.5 | length 6.9
  Top Layer w0.5: C68.2@3.875,78.232 R101.2@3.875,79.756 7.708,79.756 8.001,80.049 U9.5@8.001,81.186
NetC71_2: C71.2 R104.1 U8.3 | length 5.4
  Top Layer w0.5: U8.3@10.541,42.959 10.554,42.972 10.554,44.082 11.362,44.89 C71.2@11.362,45.331 ; C71.2@11.432,45.401 12.534,45.401 12.827,45.694 12.827,46.728 12.897,46.798 R104.1@12.954,46.798
NetC72_2: C72.2 R105.1 U8.1 | length 5.2
  Top Layer w0.5: U8.1@13.081,42.959 13.131,43.009 13.131,43.776 13.424,44.069 C72.2@14.413,44.069 R105.1@14.413,46.99
NetC75_2: C75.2 D9.3 JP10.1 R114.1 R115.1 R116.1 R117.2 | length 19.5
  Top Layer w0.4: R115.1@81.029,129.413 R117.2@82.612,129.413 C75.2@82.612,132.461 82.612,133.539 83.185,134.112 85.415,134.112 85.649,133.878 85.649,133.777 85.949,133.477 D9.3@86.149,133.477 89.724,133.477 89.997,133.204 89.997,133.024 90.117,132.904 R114.1@90.297,132.904 ; R116.1@90.297,131.687 90.486,131.498 R116.1@90.486,131.318
  Top Layer w0.5: JP10.1@89.027,128.524 89.074,128.571 89.074,129.906 90.236,131.068 90.416,131.068 90.486,131.138 R116.1@90.486,131.318 ; R116.1@90.297,131.687 R114.1@90.297,132.904
NetC76_2: C76.2 JP10.2 R118.2 | length 4.1
  Top Layer w0.4: R118.2@87.122,126.351 87.201,126.43 C76.2@88.773,126.43
  Top Layer w0.5: JP10.2@86.487,128.524 86.487,128.159 86.917,127.728 86.917,127.586 87.122,127.381 R118.2@87.122,126.351
NetC79_1: C79.1 R119.1 R126.2 TP6.1 U10.4 | length 9.3
  Top Layer w0.4: TP6.1@-19.05,40.894 -17.653,40.894 -16.328,39.569 -15.621,39.569 -15.357,39.305 -15.357,38.725 C79.1@-15.24,38.608 R119.1@-14.227,38.608 -14.227,37.461 -13.987,37.221 -13.446,37.221 -13.436,37.211 -13.081,37.211 -12.988,37.118 -12.503,37.118 U10.4@-12.403,37.018
NetC80_2: C80.2 D10.3 JP12.1 R120.1 R124.2 U10.3 | length 26.4
  Top Layer w0.5: U10.3@-10.203,37.018 -8.929,37.018 -8.636,37.311 -8.636,38.862 -6.477,41.021 -5.08,41.021 -3.98,42.121 D10.3@-3.98,44.831 -3.98,45.804 -3.302,46.482 C80.2@-3.302,48.068 -1.843,48.068 -1.397,48.514 -1.397,49.149 -1.016,49.53 JP12.1@0.381,49.53 2.032,49.53 2.986,50.484 R124.2@4.318,50.484 R120.1@4.318,52.448
NetC83_2: C83.2 D11.3 JP13.1 R122.1 R123.1 R127.1 R130.2 | length 20.3
  Top Layer w0.4: D11.3@86.53,80.264 89.89,80.264 90.124,80.03 90.124,79.938 90.244,79.818 R122.1@90.424,79.818
  Top Layer w0.5: R123.1@81.599,77.47 R130.2@82.739,77.47 C83.2@82.739,80.264 82.739,81.622 83.032,81.915 86.106,81.915 86.53,81.491 D11.3@86.53,80.264 ; JP13.1@88.9,75.565 89.139,75.804 90.282,75.804 90.486,76.008 R127.1@90.486,78.359 90.424,78.421 R122.1@90.424,79.818
NetC84_2: C84.2 JP13.2 R131.2 | length 3.8
  Top Layer w0.4: R131.2@86.36,73.392 R131.2@86.408,73.344
  Top Layer w0.5: R131.2@86.36,73.392 JP13.2@86.36,75.565 ; R131.2@86.408,73.344 C84.2@88.011,73.344
NetC88_2: C88.2 D12.3 JP15.1 R132.1 R133.1 R134.1 R136.2 | length 20
  Top Layer w0.4: D12.3@86.911,52.705 90.525,52.705 90.759,52.471 90.759,52.314 R132.1@90.879,52.194 ; R134.1@90.613,50.419 90.678,50.484 90.678,51.308 90.878,51.508 R132.1@90.878,52.193
  Top Layer w0.5: R133.1@81.599,49.784 R136.2@83.374,49.784 C88.2@83.374,52.832 83.374,53.783 83.82,54.229 86.106,54.229 86.673,53.662 86.673,52.943 D12.3@86.911,52.705 ; JP15.1@89.535,47.625 89.94,48.03 89.94,49.007 89.955,49.022 90.043,49.022 90.586,49.565 90.586,50.392 R134.1@90.613,50.419
NetC89_2: C89.2 JP15.2 R137.2 | length 4.1
  Top Layer w0.5: JP15.2@86.995,47.625 86.995,45.593 R137.2@86.868,45.466 88.711,45.466 C89.2@88.773,45.404
NetC91_2: C91.2 R135.1 R139.2 U12.3 | length 5.2
  Top Layer w0.5: R135.1@90.805,92.137 R139.2@90.805,90.997 92.687,90.997 C91.2@92.71,91.02 92.815,91.125 U12.3@94.785,91.125
NetC93_1: C93.1 CN2.5 D13.3 | length 6.4
  Top Layer w0.7: CN2.5@-40.005,70.231 -40.132,70.358 C93.1@-40.132,74.422 -40.132,76.37 D13.3@-40.005,76.497
NetC94_1: C94.1 R138.1 U12.1 | length 5.9
  Top Layer w0.4: U12.1@94.785,93.025 94.885,92.925 95.543,92.925 96.266,92.202 97.155,92.202 97.409,91.948 98.49,91.948 C94.1@98.552,91.886
  Top Layer w0.5: C94.1@98.552,91.886 R138.1@100.203,91.886
NetC96_1: C96.1 R152.2 R153.1 | length 5.6
  Top Layer w0.5: R152.2@64.516,138.303 C96.1@66.04,138.303 66.04,140.335 66.71,141.005 R153.1@67.818,141.005
NetC97_1: C97.1 R146.1 R153.2 U13.3 | length 4.6
  Top Layer w0.5: R153.2@67.818,142.405 69.85,142.405 ; U13.3@69.784,144.188 69.784,142.471 69.85,142.405 ; C97.1@70.612,142.405 69.85,142.405
NetC100_2: C100.2 D16.3 JP16.1 R143.1 R144.1 R150.2 | length 18.5
  Top Layer w0.5: R143.1@38.862,32.828 40.705,32.828 41.402,32.131 R144.1@44.512,32.131 44.512,30.288 44.196,29.972 D16.3@44.196,27.77
  Top Layer w0.6: JP16.1@36.957,27.94 35.941,28.956 35.941,31.21 36.292,31.561 C100.2@37.465,31.561 R150.2@38.862,31.561 R143.1@38.862,32.828
NetC101_2: C101.2 JP16.2 R151.2 | length 5.7
  Top Layer w0.6: JP16.2@36.957,25.4 37.084,25.273 R151.2@39.652,25.273 39.652,27.908 39.813,28.069 C101.2@39.813,28.194
NetC102_2: C102.2 R154.2 R155.2 | length 3.5
  Top Layer w0.4: R155.2@60.833,141.845 R154.2@60.833,143.637 61.013,143.637 61.267,143.891 C102.2@62.481,143.891
NetC105_2: C105.2 R156.2 R157.1 | length 6.5
  Top Layer w0.5: R157.1@71.882,143.253 C105.2@71.882,138.241 R156.2@73.406,138.241
NetC106_1: C106.1 R154.1 R158.2 U13.1 | length 15.1
  Top Layer w0.5: R154.1@60.833,145.037 65.656,145.037 66.548,144.145 67.841,144.145 67.934,144.238 67.934,144.896 68.326,145.288 68.37,145.288 68.834,145.752 68.834,147.701 69.085,147.952 R158.2@69.085,149.733 69.023,149.795 C106.1@69.023,151.257
NetC106_2: C106.2 R157.2 R158.1 U13.4 | length 8.5
  Top Layer w0.5: U13.4@69.784,146.388 70.601,146.388 ; C106.2@70.423,151.257 70.423,149.795 R158.1@70.485,149.733 70.485,147.193 70.612,147.066 70.612,146.399 70.601,146.388 ; R157.2@71.882,144.653 71.882,145.923 71.417,146.388 70.601,146.388
NetC110_1: C110.1 R165.2 R167.1 | length 5.4
  Top Layer w0.4: R165.2@64.335,100.933 65.856,100.933 C110.1@65.859,100.93 65.859,103.07 66.294,103.505 R167.1@67.437,103.505
NetC112_1: C112.1 R166.2 R168.1 | length 5.3
  Top Layer w0.5: R166.2@64.262,61.025 C112.1@65.786,61.025 65.85,61.089 65.85,61.683 66.143,61.976 67.144,61.976 67.437,62.269 R168.1@67.437,63.562
NetC114_1: C114.1 R162.1 R167.2 U14.3 | length 5
  Top Layer w0.4: R167.2@67.437,104.905 69.08,104.905 70.293,104.905 C114.1@70.358,104.84
  Top Layer w0.5: R162.1@68.961,104.902 69.077,104.902 69.08,104.905 69.147,104.972 69.147,105.596 69.27,105.719 69.27,106.717 U14.3@69.276,106.723
NetC115_1: C115.1 R164.1 R168.2 U15.3 | length 5.1
  Top Layer w0.4: R168.2@67.437,64.962 R164.1@68.961,64.962 C115.1@70.285,64.962 ; U15.3@70.165,67.099 70.165,65.082 C115.1@70.285,64.962 ; C115.1@70.358,64.962 C115.1@70.285,64.962
NetC117_2: C117.2 R169.2 R170.2 | length 3.1
  Top Layer w0.4: R169.2@60.833,107.061 R170.2@60.833,105.777 61.021,105.965 61.769,105.965 61.976,106.172 62.1,106.172 62.109,106.181 62.234,106.181 62.354,106.301 C117.2@62.354,106.426
NetC118_2: C118.2 R171.2 R172.2 | length 2.9
  Top Layer w0.4: R171.2@60.833,67.753 R172.2@60.833,66.647 61.058,66.647 61.467,67.056 C118.2@62.419,67.056
NetC120_2: C120.2 R174.2 R175.1 | length 6.7
  Top Layer w0.4: R175.1@71.882,106.107 C120.2@71.882,100.903 R174.2@73.406,100.903
NetC121_2: C121.2 R176.2 R177.1 | length 7.5
  Top Layer w0.5: C121.2@71.882,61.025 C121.2@71.939,61.025 ; R177.1@72.009,66.929 72.009,61.095 C121.2@71.939,61.025 ; R176.2@73.406,61.025 C121.2@71.939,61.025
NetC122_1: C122.1 R169.1 R179.2 U14.1 | length 14.4
  Top Layer w0.4: R169.1@60.833,108.461 63.243,108.461 64.008,107.696 67.437,107.696 ; U14.1@67.376,106.723 67.419,106.766 67.419,107.678 67.437,107.696 ; C122.1@70.293,112.014 R179.2@70.293,110.617 68.834,110.617 68.326,110.109 68.326,108.331 67.691,107.696 67.437,107.696
NetC122_2: C122.2 R175.2 R179.1 U14.4 | length 7.1
  Top Layer w0.5: U14.4@69.276,108.923 71.544,108.923 71.693,108.774 ; C122.2@71.693,112.014 R179.1@71.693,110.617 71.693,108.774 ; R175.2@71.882,107.507 71.882,108.585 71.693,108.774
NetC123_1: C123.1 R171.1 R180.2 U15.1 | length 15.3
  Top Layer w0.4: R171.1@60.833,69.153 63.562,69.153 65.616,67.099 U15.1@68.265,67.099 68.365,67.199 68.365,67.73 68.515,67.88 68.515,67.915 69.088,68.488 69.088,70.993 68.831,71.25 R180.2@68.831,72.263 C123.1@68.831,73.66
NetC123_2: C123.2 R177.2 R180.1 U15.4 | length 7
  Top Layer w0.4: C123.2@70.231,73.66 R180.1@70.231,72.263 70.231,69.365 U15.4@70.165,69.299 71.544,69.299 71.828,69.015 71.828,68.449 71.948,68.329 R177.2@72.009,68.329
NetCN1_A13: CN1.A13 R34.1 | length 14
  Top Layer w0.4: R34.1@62.23,13.73 62.23,11.984 62.8,11.414 62.8,10.361 63.161,10 65.214,10 65.8,9.414 65.8,8.082 66.274,7.607 69.693,7.607 CN1.A13@70.8,6.5
NetCN1_A14: CN1.A14 R37.1 | length 19.1
  Top Layer w0.4: R37.1@58.928,13.73 58.928,11.684 58.8,11.556 58.8,10.414 59.8,9.414 59.8,8.586 60.636,7.75 60.964,7.75 61.8,6.914 61.8,6.086 62.386,5.5 63.3,5.5 64.214,5.5 64.8,4.914 64.8,4.086 65.386,3.5 68.214,3.5 69.061,4.347 69.647,4.347 CN1.A14@69.8,4.5
NetCN1_A15: CN1.A15 R40.1 | length 14.8
  Top Layer w0.4: R40.1@60.579,13.73 60.579,11.635 60.8,11.414 60.8,10.414 61.8,9.414 61.8,8.586 62.886,7.5 65.214,7.5 65.8,6.914 65.8,6.086 66.386,5.5 67.386,5.5 67.8,5.5 CN1.A15@68.8,6.5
